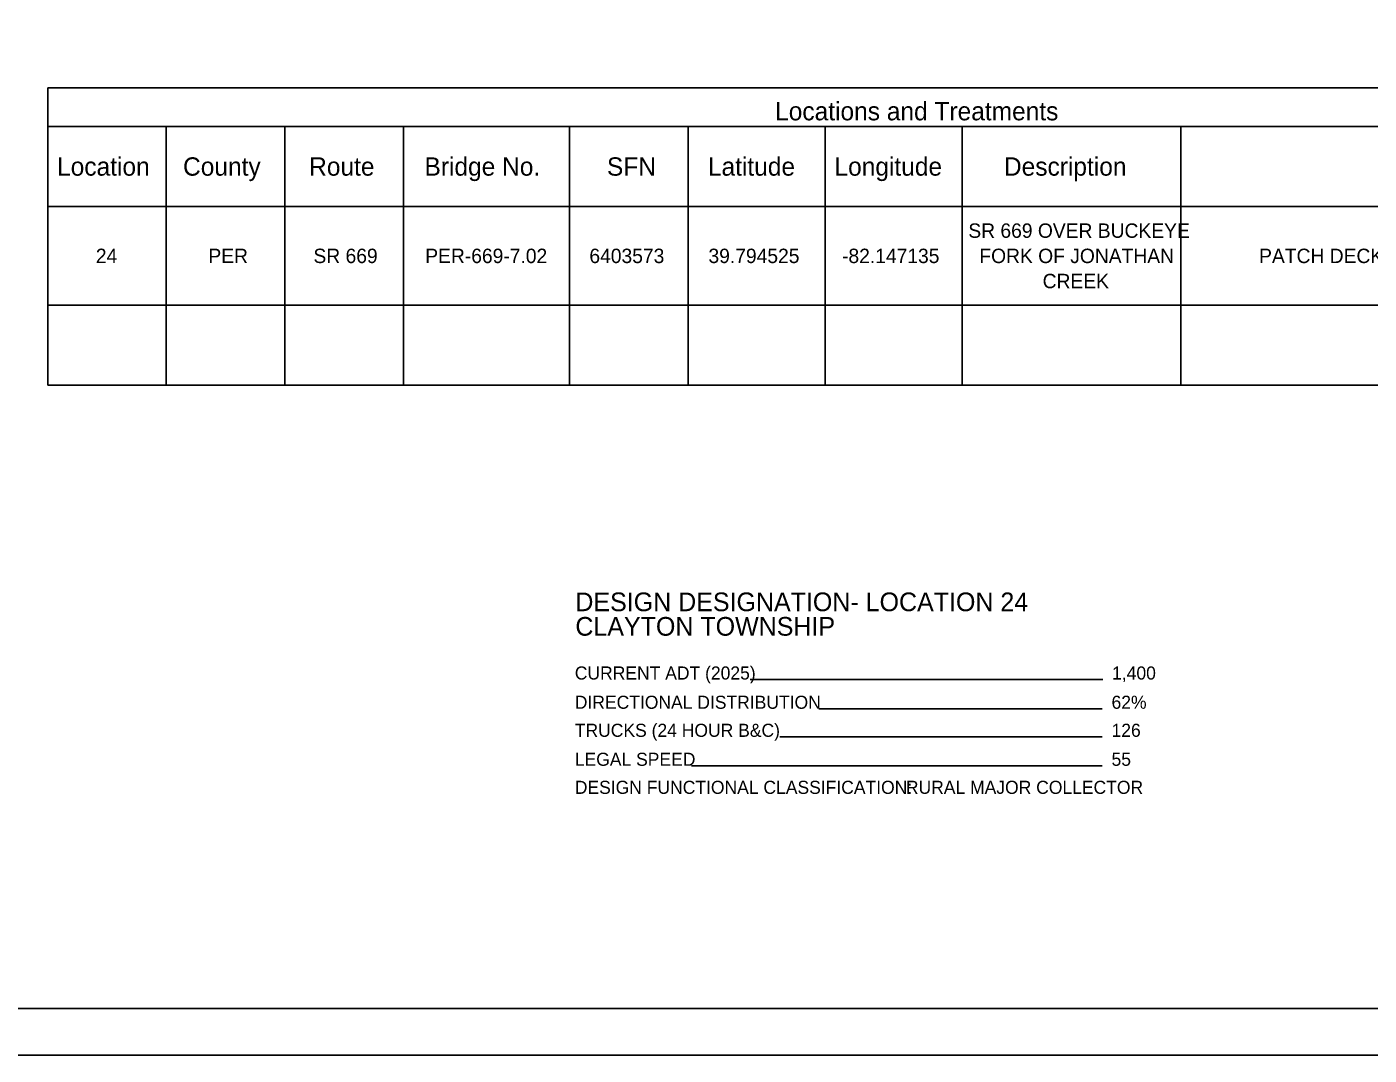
# Model space of a CAD drawing. Extents: x 0 to 34, y 0 to 22.
# Drawn here: x 7.94 to 22.3, y 0 to 11 of the extents above; entities that cross this region are included whole.
import ezdxf

# ---------------------------------------------------------------- set-up
doc = ezdxf.new("R2010")
doc.units = 0
for name, color, linetype in [('SH_Border', 7, 'Continuous'), ('SH_Cut_Line', 7, 'Continuous'), ('SH_Data', 7, 'Continuous'), ('SH_Text', 7, 'Continuous')]:
    doc.layers.add(name, color=color, linetype=linetype)

msp = doc.modelspace()

# ---------------------------------------------------------------- linework, layer by layer
at = {"layer": 'SH_Border'}
msp.add_lwpolyline([(1.5, 21.5), (33.5, 21.5), (33.5, 0.5), (1.5, 0.5)], close=True, dxfattribs=at)
at = {"layer": 'SH_Cut_Line'}
msp.add_lwpolyline([(0, 0), (34, 0), (34, 22), (0, 22)], close=True, dxfattribs=at)
at = {"layer": 'SH_Data'}
for p, q in [((19.448, 4.018), (15.677, 4.018)), ((19.442, 3.705), (16.409, 3.705)), ((19.442, 3.405), (15.994, 3.405)), ((19.442, 3.095), (15.048, 3.095))]:
    msp.add_line(p, q, dxfattribs=at)
at = {"layer": 'SH_Text'}
for p, q in [((8.161, 10.346), (27.003, 10.346)), ((8.161, 10.346), (8.161, 7.167)), ((8.161, 9.934), (27.003, 9.934)), ((9.429, 9.934), (9.429, 7.167)), ((10.697, 9.934), (10.697, 7.167)), ((11.966, 9.934), (11.966, 7.167)), ((13.744, 9.934), (13.744, 7.167)), ((15.013, 9.934), (15.013, 7.167)), ((16.479, 9.934), (16.479, 7.167)), ((17.944, 9.934), (17.944, 7.167)), ((20.283, 9.934), (20.283, 7.167)), ((8.161, 9.077), (27.003, 9.077)), ((8.161, 8.023), (27.003, 8.023)), ((8.161, 7.167), (27.003, 7.167))]:
    msp.add_line(p, q, dxfattribs=at)

# ---------------------------------------------------------------- texts
at = {"layer": 'SH_Data'}
for s, p in [('DESIGN DESIGNATION- LOCATION 24', (13.806, 4.749)), ('CLAYTON TOWNSHIP', (13.806, 4.487))]:
    msp.add_text(s, height=0.2, dxfattribs=at).set_placement(p)
at = {"layer": 'SH_Text'}
for s, height, p in [('Locations and Treatments', 0.196, (15.943, 10)), ('Location', 0.196, (8.261, 9.408)), ('County', 0.196, (9.609, 9.408)), ('Route', 0.196, (10.958, 9.408)), ('Bridge No.', 0.196, (12.192, 9.408)), ('SFN', 0.196, (14.144, 9.408)), ('Latitude', 0.196, (15.224, 9.408)), ('Longitude', 0.196, (16.578, 9.408)), ('Description', 0.196, (18.391, 9.408)), ('SR 669 OVER BUCKEYE ', 0.154, (18.01, 8.743)), ('24', 0.154, (8.676, 8.473)), ('PER', 0.154, (9.88, 8.473)), ('SR 669', 0.154, (11.004, 8.473)), ('PER-669-7.02', 0.154, (12.2, 8.473)), ('6403573', 0.154, (13.956, 8.473)), ('39.794525', 0.154, (15.23, 8.473)), ('-82.147135', 0.154, (16.659, 8.473)), ('FORK OF JONATHAN ', 0.154, (18.128, 8.473)), ('PATCH DECK AND DECK EDGES, SEAL WITH HMWM.', 0.154, (21.121, 8.473)), ('CREEK', 0.154, (18.805, 8.204)), ('CURRENT ADT (2025)', 0.14, (13.8, 4.018)), ('1,400', 0.14, (19.548, 4.018)), ('DIRECTIONAL DISTRIBUTION', 0.14, (13.8, 3.705)), ('62%', 0.14, (19.542, 3.705)), ('TRUCKS (24 HOUR B&C)', 0.14, (13.8, 3.405)), ('126', 0.14, (19.542, 3.405)), ('LEGAL SPEED', 0.14, (13.8, 3.095)), ('55', 0.14, (19.542, 3.095)), ('DESIGN FUNCTIONAL CLASSIFICATION:', 0.14, (13.8, 2.795)), ('RURAL MAJOR COLLECTOR', 0.14, (17.342, 2.795))]:
    msp.add_text(s, height=height, dxfattribs=at).set_placement(p)

doc.saveas('drawing.dxf')
